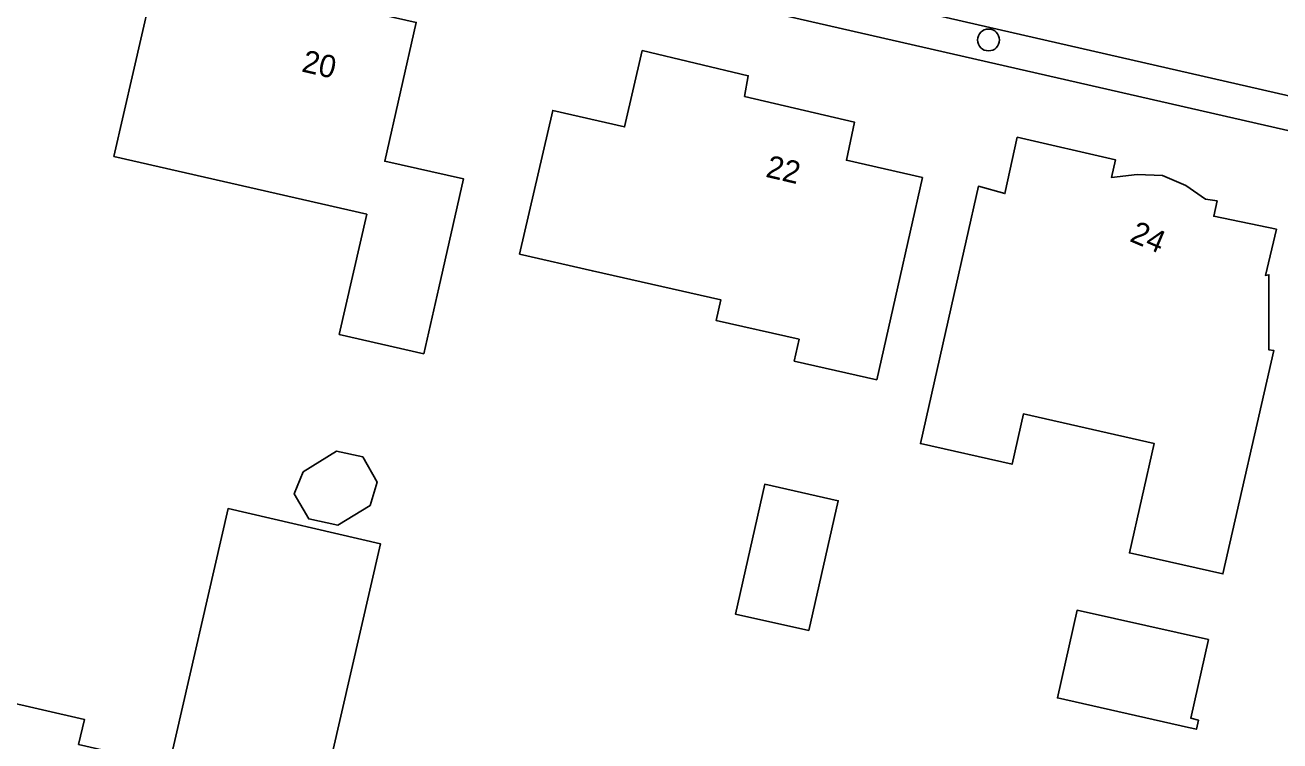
# Model space of a CAD drawing. Extents: x 159626 to 160723, y 388173 to 389416.
# Drawn here: x 160184.1 to 160240.2, y 388762.4 to 388794.4 of the extents above; entities that cross this region are included whole.
import ezdxf

# ---------------------------------------------------------------- set-up
doc = ezdxf.new("R2010")
doc.units = 0
for name, color, linetype in [('IMGEO_Boom', 7, 'Continuous'), ('IMGEO_Erf', 7, 'Continuous'), ('IMGEO_Pand', 7, 'Continuous'), ('IMGEO_Pand_nummerreeks', 7, 'Continuous'), ('IMGEO_Rijbaan_lokaal_open', 7, 'Continuous'), ('IMGEO_Voetpad_open', 7, 'Continuous')]:
    doc.layers.add(name, color=color, linetype=linetype)

msp = doc.modelspace()

# ---------------------------------------------------------------- linework, layer by layer
at = {"layer": 'IMGEO_Boom'}
msp.add_circle((160227.135, 388793.76), 0.489, dxfattribs=at)
at = {"layer": 'IMGEO_Erf'}
msp.add_lwpolyline([(160245.477, 388788.575), (160212.187, 388796.199), (160181.552, 388803.215)], dxfattribs=at)
for points in [[(160199.34, 388785.97), (160188.037, 388788.556), (160188.895, 388792.306), (160190.01, 388797.18), (160190.81, 388796.986), (160190.943, 388797.552), (160194.406, 388796.76), (160194.285, 388796.199), (160201.555, 388794.544), (160200.144, 388788.343), (160203.671, 388787.551), (160202.557, 388782.677), (160201.886, 388779.738), (160198.112, 388780.602)], [(160209.427, 388783.442), (160206.171, 388784.193), (160207.651, 388790.613), (160210.867, 388789.871), (160211.653, 388793.282), (160216.394, 388792.157), (160216.23, 388791.233), (160221.147, 388790.08), (160220.78, 388788.381), (160224.178, 388787.606), (160223.077, 388782.729), (160222.14, 388778.575), (160218.447, 388779.409), (160218.667, 388780.383), (160214.965, 388781.219), (160215.174, 388782.144)], [(160225.582, 388782.342), (160226.682, 388787.219), (160227.863, 388786.896), (160228.415, 388789.41), (160232.81, 388788.401), (160232.625, 388787.614), (160233.783, 388787.748), (160234.916, 388787.702), (160235.956, 388787.261), (160236.824, 388786.651), (160237.346, 388786.564), (160237.198, 388785.885), (160240.002, 388785.299), (160239.512, 388783.241), (160239.665, 388783.27), (160239.665, 388779.907), (160239.89, 388779.878), (160237.611, 388769.901), (160233.427, 388770.838), (160234.531, 388775.732), (160228.692, 388777.049), (160228.185, 388774.802), (160224.089, 388775.726)], [(160196.492, 388774.465), (160197.992, 388775.38), (160199.158, 388775.126), (160199.804, 388773.995), (160199.496, 388772.96), (160198.05, 388772.073), (160196.746, 388772.356), (160196.102, 388773.483)], [(160219.107, 388767.366), (160215.821, 388768.107), (160217.131, 388773.909), (160220.416, 388773.168)], [(160180.46, 388760.11), (160180.05, 388760.24), (160181.075, 388764.695), (160186.717, 388763.397), (160186.459, 388762.278), (160190.506, 388761.347), (160193.144, 388772.816), (160199.948, 388771.25), (160196.448, 388756.04), (160195.327, 388751.167), (160190.749, 388752.143), (160190.537, 388751.642), (160190.157, 388751.707), (160187.8, 388752.276), (160187.146, 388753.209), (160184.273, 388753.861), (160184.077, 388753.118), (160179.142, 388754.228)], [(160231.09, 388768.28), (160232.765, 388767.904), (160236.961, 388766.962), (160236.171, 388763.458), (160236.513, 388763.364), (160236.426, 388762.959), (160236.069, 388763.039), (160230.21, 388764.36)]]:
    msp.add_lwpolyline(points, close=True, dxfattribs=at)
at = {"layer": 'IMGEO_Pand'}
for points in [[(160202.557, 388782.677), (160203.671, 388787.551), (160200.144, 388788.343), (160201.555, 388794.544), (160194.285, 388796.199), (160194.406, 388796.76), (160190.943, 388797.552), (160190.81, 388796.986), (160190.01, 388797.18), (160188.895, 388792.306), (160188.037, 388788.556), (160199.34, 388785.97), (160198.112, 388780.602), (160201.886, 388779.738)], [(160223.077, 388782.729), (160224.178, 388787.606), (160220.78, 388788.381), (160221.147, 388790.08), (160216.23, 388791.233), (160216.394, 388792.157), (160211.653, 388793.282), (160210.867, 388789.871), (160207.651, 388790.613), (160206.171, 388784.193), (160209.427, 388783.442), (160215.174, 388782.144), (160214.965, 388781.219), (160218.667, 388780.383), (160218.447, 388779.409), (160222.14, 388778.575)], [(160225.582, 388782.342), (160224.089, 388775.726), (160228.185, 388774.802), (160228.692, 388777.049), (160234.531, 388775.732), (160233.427, 388770.838), (160237.611, 388769.901), (160239.89, 388779.878), (160239.665, 388779.907), (160239.665, 388783.27), (160239.512, 388783.241), (160240.002, 388785.299), (160237.198, 388785.885), (160237.346, 388786.564), (160236.824, 388786.651), (160235.956, 388787.261), (160234.916, 388787.702), (160233.783, 388787.748), (160232.625, 388787.614), (160232.81, 388788.401), (160228.415, 388789.41), (160227.863, 388786.896), (160226.682, 388787.219)], [(160196.492, 388774.465), (160196.102, 388773.483), (160196.746, 388772.356), (160198.05, 388772.073), (160199.496, 388772.96), (160199.804, 388773.995), (160199.158, 388775.126), (160197.992, 388775.38)], [(160219.107, 388767.366), (160220.416, 388773.168), (160217.131, 388773.909), (160215.821, 388768.107)], [(160195.327, 388751.167), (160196.448, 388756.04), (160199.948, 388771.25), (160193.144, 388772.816), (160190.506, 388761.347), (160186.459, 388762.278), (160186.717, 388763.397), (160181.075, 388764.695), (160180.05, 388760.24), (160180.46, 388760.11), (160179.142, 388754.228), (160184.077, 388753.118), (160184.273, 388753.861), (160187.146, 388753.209), (160187.8, 388752.276), (160190.157, 388751.707), (160190.537, 388751.642), (160190.749, 388752.143)], [(160232.765, 388767.904), (160231.09, 388768.28), (160230.21, 388764.36), (160236.069, 388763.039), (160236.426, 388762.959), (160236.513, 388763.364), (160236.171, 388763.458), (160236.961, 388766.962)]]:
    msp.add_lwpolyline(points, close=True, dxfattribs=at)
at = {"layer": 'IMGEO_Rijbaan_lokaal_open'}
msp.add_lwpolyline([(160259.458, 388786.946), (160269.969, 388784.539), (160271.082, 388789.403), (160213.639, 388802.545), (160212.526, 388797.678), (160245.83, 388790.053)], dxfattribs=at)
at = {"layer": 'IMGEO_Voetpad_open'}
for points in [[(160245.83, 388790.053), (160212.526, 388797.678), (160209.868, 388798.287), (160181.886, 388804.693)], [(160181.552, 388803.215), (160212.187, 388796.199), (160245.477, 388788.575), (160248.339, 388787.931)]]:
    msp.add_lwpolyline(points, dxfattribs=at)

# ---------------------------------------------------------------- texts
at = {"layer": 'IMGEO_Pand_nummerreeks'}
for s, rotation, p in [('20', 347.1753, (160196.389, 388792.356)), ('22', 346.803, (160217.132, 388787.652)), ('24', 337.0212, (160233.395, 388784.785))]:
    msp.add_text(s, height=1, rotation=rotation, dxfattribs=at).set_placement(p)

doc.saveas('drawing.dxf')
